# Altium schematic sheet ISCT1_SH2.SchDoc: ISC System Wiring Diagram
size B; DrawnBy: Filiberto Clara; Engineer: Filiberto Clara; Organization: LIGO Laboratory; Address1: California Institute of Technology; Address2: Massachusetts Institute of Technology; SheetNumber: 23; SheetTotal: 37
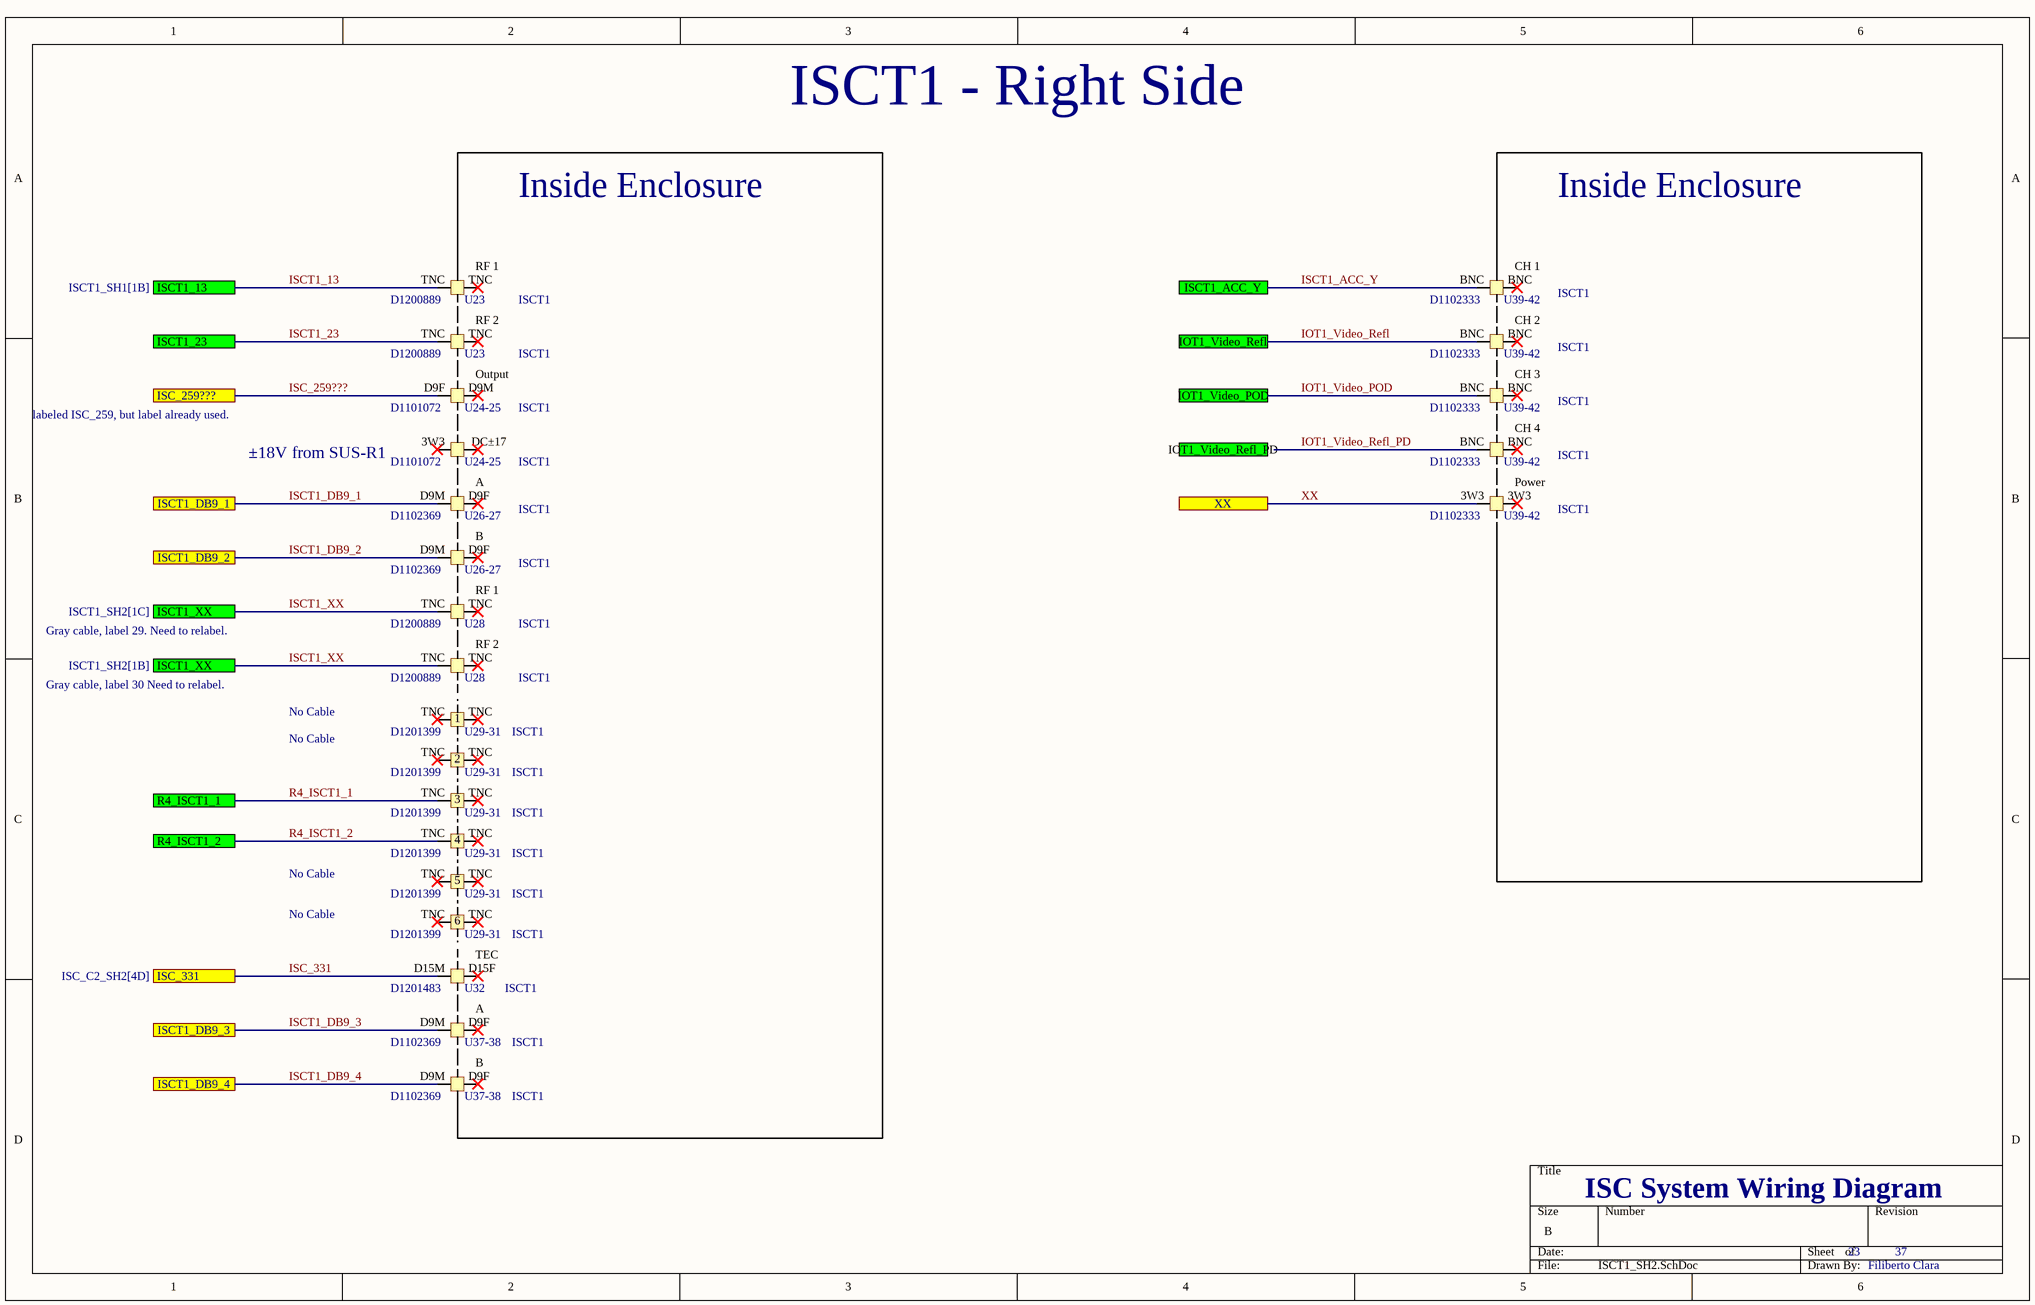
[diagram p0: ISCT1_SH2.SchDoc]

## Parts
C_ISCT1_5  DCC: D1200889  Rack: ISCT1  Slot: U23  (hidden comment: Patch Panel Broadband PD)  (parts A,B of 2)
C_ISCT1_6  DCC: D1101072  Rack: ISCT1  Slot: U24-25  (hidden comment: Patch Panel DCPD Interface)  (parts A,B of 2)
C_ISCT1_7  DCC: D1102369  Rack: ISCT1  Slot: U26-27  (hidden comment: Patch Panel Uniblitz Shutters)  (parts A,B of 2)
C_ISCT1_8  DCC: D1200889  Rack: ISCT1  Slot: U28  (hidden comment: Patch Panel Broadband PD)  (parts A,B of 2)
C_ISCT1_9  DCC: D1201399  Rack: ISCT1  Slot: U29-31  (hidden comment: Patch Panel DCPD)  (parts A,B,C,D,E,F of 6)
C_ISCT1_10  DCC: D1201483  Rack: ISCT1  Slot: U32  (hidden comment: Patch Panel TEC Driver)
C_ISCT1_11  DCC: D1102369  Rack: ISCT1  Slot: U37-38  (hidden comment: Patch Panel Uniblitz Shutters)  (parts A,B of 2)
C_ISCT1_12  DCC: D1102333  Rack: ISCT1  Slot: U39-42  (hidden comment: Patch Panel Analog Video)  (parts A,B,C,D,E of 5)

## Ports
IOT1_Video_POD, IOT1_Video_Refl, IOT1_Video_Refl_PD, ISC_259???, ISC_331 (see ISC_C2_SH2[4D]), ISCT1_13 (see ISCT1_SH1[1B]), ISCT1_23, ISCT1_ACC_Y, ISCT1_DB9_1, ISCT1_DB9_2, ISCT1_DB9_3, ISCT1_DB9_4, ISCT1_XX (see ISCT1_SH2[1B]), ISCT1_XX (see ISCT1_SH2[1C]), R4_ISCT1_1, R4_ISCT1_2, XX

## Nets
IOT1_Video_POD: C_ISCT1_12.BNC(CH_3) ; port IOT1_Video_POD
IOT1_Video_Refl: C_ISCT1_12.BNC(CH_2) ; port IOT1_Video_Refl
IOT1_Video_Refl_PD: C_ISCT1_12.BNC(CH_4)
ISC_259???: C_ISCT1_6.D9F(Output) ; port ISC_259???
ISC_331: C_ISCT1_10.D15M(TEC) ; port ISC_331
ISCT1_13: C_ISCT1_5.TNC(RF1) ; port ISCT1_13
ISCT1_23: C_ISCT1_5.TNC(RF2) ; port ISCT1_23
ISCT1_ACC_Y: C_ISCT1_12.BNC(CH_1) ; port ISCT1_ACC_Y
ISCT1_DB9_1: C_ISCT1_7.D9M(Output) ; port ISCT1_DB9_1
ISCT1_DB9_2: C_ISCT1_7.D9M(B) ; port ISCT1_DB9_2
ISCT1_DB9_3: C_ISCT1_11.D9M(Output) ; port ISCT1_DB9_3
ISCT1_DB9_4: C_ISCT1_11.D9M(B) ; port ISCT1_DB9_4
ISCT1_XX: C_ISCT1_8.TNC(RF1) ; port ISCT1_XX
R4_ISCT1_1: C_ISCT1_9.TNC ; port R4_ISCT1_1
R4_ISCT1_2: C_ISCT1_9.TNC ; port R4_ISCT1_2
XX: C_ISCT1_12.3W3(Power) ; port XX

Not connected (* = marked no-connect by the designer): C_ISCT1_6 3W3(DC±17)* D9M(Output)*; C_ISCT1_7 D9F(Output)*; C_ISCT1_10 D15F(TEC)*; C_ISCT1_11 D9F(Output)*

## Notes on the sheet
- ISCT1 - Right Side
- Inside Enclosure
- labeled ISC_259, but label already used.
- ±18V from SUS-R1
- Gray cable, label 29. Need to relabel.
- Gray cable, label 30 Need to relabel.
- No Cable

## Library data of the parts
C_ISCT1_5 C_ISCT1_8 = Patch Panel Broadband PD: Patch Panel (D1200889); Serial: Sxxxxxxx; System: ISC
C_ISCT1_6 = Patch Panel DCPD Interface: Patch Panel (D1101072); Serial: Sxxxxxxx; System: ISC
C_ISCT1_7 C_ISCT1_11 = Patch Panel Uniblitz Shutters: Patch Panel (D1102369); Serial: Sxxxxxxx; System: ISC
C_ISCT1_9 = Patch Panel DCPD: Patch Panel (D1201399); Serial: Sxxxxxxx; System: ISC
C_ISCT1_10 = Patch Panel TEC Driver: Patch Panel (D1201483); Serial: Sxxxxxxx; System: ISC
C_ISCT1_12 = Patch Panel Analog Video: Patch Panel (D1102333); Serial: Sxxxxxxx; System: ISC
